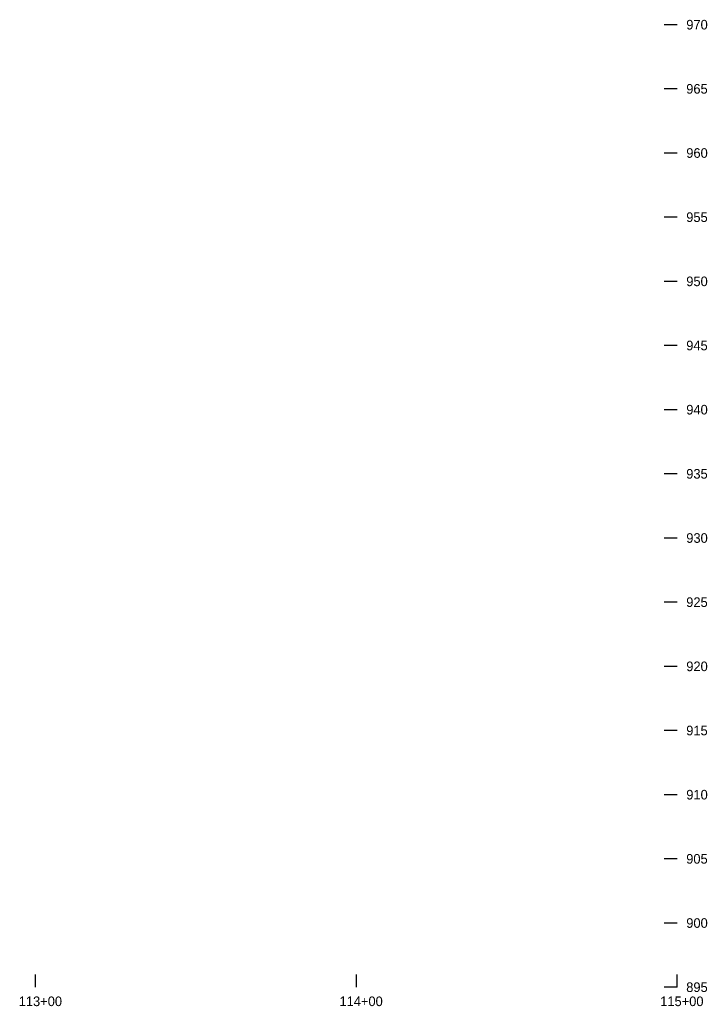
# Model space of a CAD drawing. Extents: x 2091593 to 2093109, y 1330214 to 1331965.
# Drawn here: x 2092894.7 to 2093109.1, y 1331544.3 to 1331851.7 of the extents above; entities that cross this region are included whole.
import ezdxf

# ---------------------------------------------------------------- set-up
doc = ezdxf.new("R2010")
doc.units = 0
for name, color, linetype in [('SHT_B_Grid-Elevation-Text', 7, 'Continuous'), ('SHT_B_Grid-Station-Text', 7, 'Continuous'), ('SHT_B_Major-Elevation-Tic-Line', 7, 'Continuous'), ('SHT_B_Major-Station-Tic-Line', 7, 'Continuous')]:
    doc.layers.add(name, color=color, linetype=linetype)

msp = doc.modelspace()

# ---------------------------------------------------------------- linework, layer by layer
at = {"layer": 'SHT_B_Major-Elevation-Tic-Line'}
for p, q in [((2093099.69, 1331850.21), (2093095.69, 1331850.21)), ((2093099.69, 1331850.21), (2093095.69, 1331850.21)), ((2093099.69, 1331830.21), (2093095.69, 1331830.21)), ((2093099.69, 1331810.21), (2093095.69, 1331810.21)), ((2093099.69, 1331790.21), (2093095.69, 1331790.21)), ((2093099.69, 1331770.21), (2093095.69, 1331770.21)), ((2093099.69, 1331750.21), (2093095.69, 1331750.21)), ((2093099.69, 1331730.21), (2093095.69, 1331730.21)), ((2093099.69, 1331710.21), (2093095.69, 1331710.21)), ((2093099.69, 1331690.21), (2093095.69, 1331690.21)), ((2093099.69, 1331670.21), (2093095.69, 1331670.21)), ((2093099.69, 1331650.21), (2093095.69, 1331650.21)), ((2093099.69, 1331630.21), (2093095.69, 1331630.21)), ((2093099.69, 1331610.21), (2093095.69, 1331610.21)), ((2093099.69, 1331590.21), (2093095.69, 1331590.21)), ((2093099.69, 1331570.21), (2093095.69, 1331570.21)), ((2093099.69, 1331550.21), (2093095.69, 1331550.21))]:
    msp.add_line(p, q, dxfattribs=at)
at = {"layer": 'SHT_B_Major-Station-Tic-Line'}
for p, q in [((2092899.69, 1331550.21), (2092899.69, 1331554.21)), ((2092999.69, 1331550.21), (2092999.69, 1331554.21)), ((2093099.69, 1331550.21), (2093099.69, 1331554.21))]:
    msp.add_line(p, q, dxfattribs=at)

# ---------------------------------------------------------------- texts
at = {"layer": 'SHT_B_Grid-Elevation-Text'}
for s, p in [('970', (2093102.55, 1331848.71)), ('970', (2093102.55, 1331848.71)), ('965', (2093102.53, 1331828.71)), ('960', (2093102.55, 1331808.71)), ('955', (2093102.53, 1331788.71)), ('950', (2093102.55, 1331768.71)), ('945', (2093102.53, 1331748.71)), ('940', (2093102.55, 1331728.71)), ('935', (2093102.53, 1331708.71)), ('930', (2093102.55, 1331688.71)), ('925', (2093102.53, 1331668.71)), ('920', (2093102.55, 1331648.71)), ('915', (2093102.53, 1331628.71)), ('910', (2093102.55, 1331608.71)), ('905', (2093102.53, 1331588.71)), ('900', (2093102.55, 1331568.71)), ('895', (2093102.53, 1331548.71))]:
    msp.add_text(s, height=3, dxfattribs=at).set_placement(p)
at = {"layer": 'SHT_B_Grid-Station-Text'}
for s, p in [('113+00', (2092894.42, 1331544.31)), ('114+00', (2092994.42, 1331544.31)), ('115+00', (2093094.42, 1331544.31))]:
    msp.add_text(s, height=3, dxfattribs=at).set_placement(p)

doc.saveas('drawing.dxf')
